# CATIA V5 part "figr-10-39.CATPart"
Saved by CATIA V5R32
Part number: Part1
Bounding box of the stored display mesh (mm): x 0 to 56, y -58.044 to 12.863, z -44.68 to 88.822
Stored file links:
  D:\PROJECTS\Project 2022\CATIA V5 6R 2022\Resources\Part Files\c10_catia_v5_6r2022_prt\c10_catia_v5_6r2022_prt\figr-10-39.CATPart
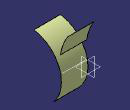
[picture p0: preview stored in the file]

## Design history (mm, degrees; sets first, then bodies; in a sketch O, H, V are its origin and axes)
Body1 (main body)
  Sketch1 on yz-plane, origin (0, 0, 0), H (0, 1, 0), V (0, 0, 1)
    arc A1 centre (-66.8734, 0) radius 66.8734 from (-58.0438, 66.2879) to (-17.1165, -44.68) cw
    coincidence: A1 O
    tangency: A1 V
  Extrude1: Element1 Sketch1, Lim1 56, Lim2 0
  Sketch2 on zx-plane, origin (0, 0, 0), H (-1, 0, 0), V (0, 0, 1)
    line L1 (-55.482, 13.9185) -> (0, 13.9185)
    point P1 (0, 13.9185)
    coincidence: P1 V
    horizontal: L1 H
  Project1: ToProject Sketch2, Support Extrude1
  Sweep1: type Circle, Guide Project1, Reference Extrude1, Radius 100, Angle1 20, Angle2 45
